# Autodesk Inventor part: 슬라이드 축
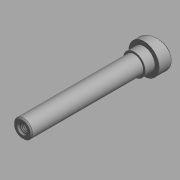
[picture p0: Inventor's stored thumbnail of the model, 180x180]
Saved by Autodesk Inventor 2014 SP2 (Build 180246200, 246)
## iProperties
Created: 2015-11
Part Number: 슬라이드 축
Document SubType Name: 모델링
Designer: mdu
Mass: 174.309 g
Surface Area: 67.586 cm^2
Volume: 21.5729 cm^3
Density: 8.08 g/cm^3
Material: 스테인리스강
Appearance: 기본값
변환 표준: STEP AP214IS
파일 이름: C:\Users\SeoGD\Desktop\?쒗뿕\異?stp
전처리기: Build: 253, Release: 2010 SP1 - Date: Wed 07/29/2009
전송 단위: 밀리미터
불확실성: 0.01
Author: mdu
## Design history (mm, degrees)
sketch "스케치1"
  geometry: L1 (0, 100)-(7.5, 100); L2 (7.5, 100)-(7.5, 0); L3 (7.5, 0)-(12.5, 0); L4 (12.5, 0)-(12.5, -17); L5 (12.5, -17)-(0, -17); L6 (0, -17)-(0, 100); 1 further point
  constraints: 12 end point, 2 parallel, 2 point on line, 1 perpendicular, 1 vertical
  dimensions: "d0" = 100 distance from line of L1 point (0, 0); "d1" = 15 diameter of L2 L6; "d2" = 25 diameter of L4 L6; "d3" = 17 distance of L3.end L4.end
revolve "회전1" sketch "스케치1" stored, may be unused: angle "d4" = 90 deg
sketch "스케치2"
  geometry: L1 (12.5, 0)-(12.5, -17) reference; L2 (-12.5, -17)-(12.5, -17) reference; L3 (-12.5, 0)-(-12.5, -17) reference; L4 (12.5, -5)-(-12.5, -11.699); L5 (-12.5, 0)-(12.5, 0) reference; 1 further point
  constraints: 2 end point, 2 point on line
  dimensions: "d5" = 75 deg angle of L1 L4; "d6" = 5 distance from line of L4.start L5
extrude "돌출1" cut sketch "스케치2" stored distance "d7" = 10; taper "d8" = 0 deg
chamfer "모따기1" distance "d9" = 1; stored, may be unused: second distance "d10" = 2, angle "d11" = 45 deg
fillet "모깎기1" dims "d12" = 0.5
hole "구멍1" diameter "d15" = 6.647; stored, may be unused: countersink angle "d19" = 90 deg, drill point angle "d21" = 118 deg; dims "d13" = 10, "d14" = 10, "d16" = 17, "d17" = 4, "d18" = 2, "d20" = 20
chamfer "모따기2" distance "d22" = 1; stored, may be unused: second distance "d23" = 2, angle "d24" = 45 deg
sketch "스케치3"
  geometry: C1 r 9 at (0, 0); 1 further point
  constraints: 1 centre point, 1 coincident
  dimensions: "d25" = 18 diameter of C1
extrude "돌출2" join sketch "스케치3" distance "d26" = 8; taper "d27" = 0 deg
node "솔리드1"
node "솔리드 본체"
node "곡면 본체"
node "솔리드2"
